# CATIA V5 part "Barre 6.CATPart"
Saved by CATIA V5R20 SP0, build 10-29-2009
Part number: Barre 6
Bounding box of the stored display mesh (mm): x -169.748 to 244.923, y -391.857 to -208.208, z -10 to 0
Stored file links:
  C:\Users\Matthieu\Desktop\IFMA\Cours 2A\Thinkmotion\Projet_IAO_714_Matthieu_Perrusset\Barre 6.CATPart
  C:\Users\Matthieu\Desktop\IFMA\Cours 2A\Thinkmotion\Ass_skl_IAO.CATProduct
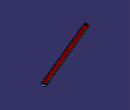
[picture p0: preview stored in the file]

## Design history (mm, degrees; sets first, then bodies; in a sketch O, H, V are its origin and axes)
AxisSystem1: origin (0, 0, 0), X (1, 0, 0), Y (0, 1, 0), Z (0, 0, 1)
Set1
  Line1 "Barre_6": linked copy from another document
  Line2 "Axe_Pivot_b6b5": linked copy from another document
  Line3 "Axe_Pivot_b6b3": linked copy from another document
Body1 (main body)
  Plane1 "Plan_Ref": stored without definition
  Sketch1 on Plane1, origin (0, 0, 0), H (1, 0, 0), V (0, 1, 0)
    line L1 (238.7534, -227.4455) -> (-155.9175, -391.094)
    arc A1 centre (-159.7477, -381.8566) radius 10 from (-155.9175, -391.094) to (-163.578, -372.6192) cw
    point P3 (-159.7477, -381.8566)
    line L2 (-163.578, -372.6192) -> (231.0929, -208.9707)
    arc A2 centre (234.9232, -218.2081) radius 10 from (231.0929, -208.9707) to (238.7534, -227.4455) cw
    point P6 (234.9232, -218.2081)
    reference projected line E1 (-159.7477, -381.8566) -> (234.9232, -218.2081) from Line1
    reference projected line E2 (-159.7477, -381.8566) -> (234.9232, -218.2081) from Line1
    reference projected point E3 (234.9232, -218.2081) from Line2
    reference projected point E4 (-159.7477, -381.8566) from Line3
    reference projected line E5 (-159.7477, -381.8566) -> (234.9232, -218.2081) from Line1
    reference projected line E6 (-159.7477, -381.8566) -> (234.9232, -218.2081) from Line1
    circle A3 centre (-159.7477, -381.8566) radius 5
    circle A4 centre (234.9232, -218.2081) radius 5
    distance E5 L1 = 10
    distance E6 L2 = 10
    distance P6 A2 = 10
    distance P3 A1 = 10
    distance A3 P3 = 5
    distance A4 P6 = 5
    parallelism: L2 L1, E1 L1, E2 L2
    coincidence: P6 E3, P3 E4
  Pad1: profile Sketch1, direction (0, 0, -1), length 0, opposite side length -10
